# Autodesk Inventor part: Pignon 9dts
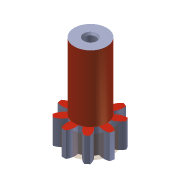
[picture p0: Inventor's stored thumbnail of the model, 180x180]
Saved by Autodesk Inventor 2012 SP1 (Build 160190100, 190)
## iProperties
Created: 2014-12
Part Number: Pignon 9dts
Material: Default
Document SubType Name: Modeling
Designer: Bruno
Density: 1 g/cm^3
Mass: 2.6379 g
Surface Area: 16.4372 cm^2
Volume: 2.6379 cm^3
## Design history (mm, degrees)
node "Pignon 9dts1"
sketch "Esquisse1"
  geometry: C1 r 2.048 at (0, 0) reference; C2 r 6.757 at (0, 0)
  constraints: 1 centre point, 1 coincident
feature "SrfExtrusion1" sketch "Esquisse1" dims "d0" = 7, "d1" = 0
node "Pignon 9dts"
node "Base1"
body "Srf1"
